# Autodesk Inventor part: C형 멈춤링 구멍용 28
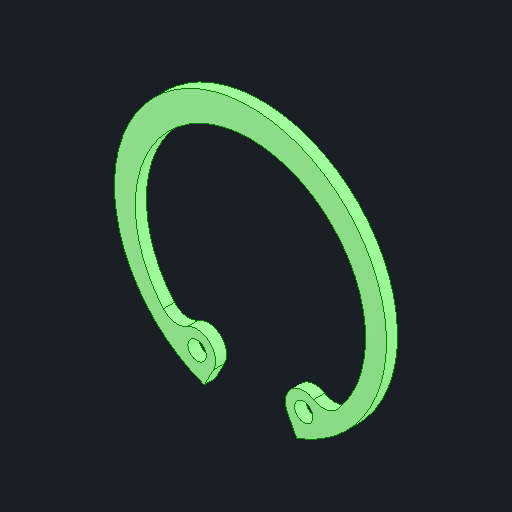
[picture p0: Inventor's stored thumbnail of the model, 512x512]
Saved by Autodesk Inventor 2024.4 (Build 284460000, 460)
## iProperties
Created: 2026-03
Part Number: C형 멈춤링 구멍용 28
Material: 강철, 연강
Description: 리테이닝 링(C형)
Document SubType Name: Modeling
Designer: user
Density: 7.85 g/cm^3
Appearance: 기본값
Author: jhkim
Sending System: Autodesk Inventor 2026
Preprocessor: ST-DEVELOPER v20.1
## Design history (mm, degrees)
feature "Solid1"
node "솔리드1"
